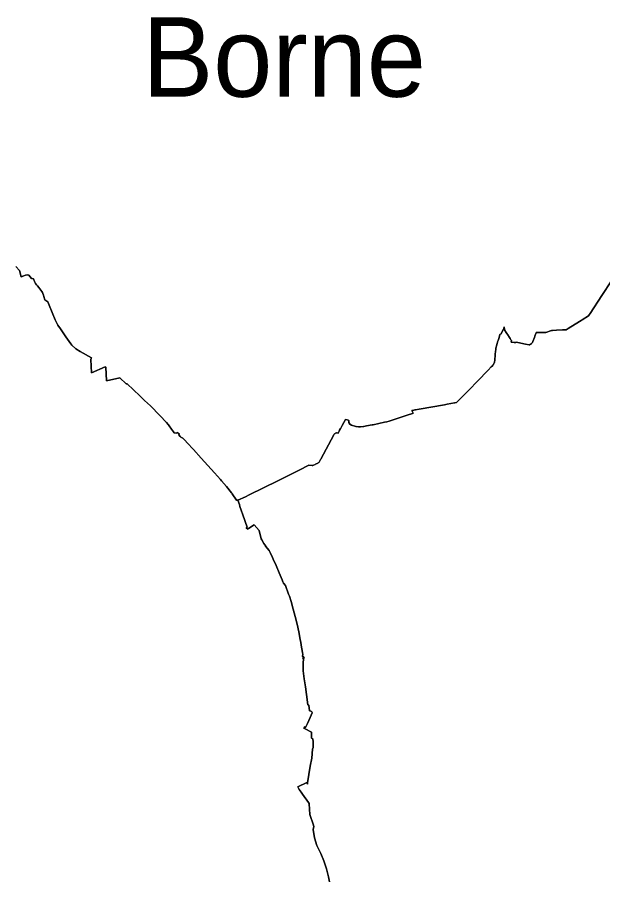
# Model space of a CAD drawing. Extents: x 113371 to 291721, y 393993 to 520143.
# Drawn here: x 246091 to 249775, y 475732 to 481156 of the extents above; entities that cross this region are included whole.
import ezdxf

# ---------------------------------------------------------------- set-up
doc = ezdxf.new("R2010")
doc.units = 0
doc.layers.add('Default', color=7, linetype='Continuous')
doc.layers.add('plaatsnamen', color=7, linetype='Continuous')

msp = doc.modelspace()

# ---------------------------------------------------------------- linework, layer by layer
at = {"layer": 'Default'}
for points in [[(246253.275625, 479417.4025), (246249.695625, 479425.5425), (246246.135625, 479431.3125), (246227.195625, 479457.0825), (246218.675625, 479466.1825), (246213.075625, 479472.6225), (246206.425625, 479481.6125), (246199.555625, 479494.6825), (246194.095625, 479509.9425), (246185.685625, 479512.2525), (246180.415625, 479513.7025), (246173.165625, 479523.2925), (246165.015625, 479532.7925), (246153.395625, 479536.4325), (246143.605625, 479534.5225), (246132.055625, 479529.7725), (246116.925625, 479522.3425), (246106.355625, 479563.2925), (246082.185625, 479588.5725)], [(246082.185625, 479588.5725), (246106.355625, 479563.2925), (246116.925625, 479522.3425), (246132.055625, 479529.7725), (246143.605625, 479534.5225), (246153.395625, 479536.4325), (246165.015625, 479532.7925), (246173.165625, 479523.2925), (246180.415625, 479513.7025), (246185.685625, 479512.2525), (246194.095625, 479509.9425), (246199.555625, 479494.6825), (246206.425625, 479481.6125), (246213.075625, 479472.6225), (246218.675625, 479466.1825), (246227.195625, 479457.0825), (246246.135625, 479431.3125), (246249.695625, 479425.5425), (246253.275625, 479417.4025), (246256.615625, 479408.5525), (246258.945625, 479399.9925), (246264.845625, 479378.1225), (246284.445625, 479365.7125), (246292.505625, 479344.5025), (246329.455625, 479252.2425)], [(249829.695625, 479499.0325), (249768.455625, 479405.4325), (249695.095625, 479293.2825), (249689.475625, 479284.7025), (249684.365625, 479276.8925), (249645.815625, 479253.0425), (249638.595625, 479248.7025), (249573.345625, 479208.2025), (249557.725625, 479198.5325), (249544.715625, 479190.4825), (249521.635625, 479190.8125), (249484.685625, 479187.6825), (249459.525625, 479186.1425), (249454.005625, 479185.8025), (249451.905625, 479185.1225)], [(249768.455625, 479405.4325), (249829.695625, 479499.0325)], [(247110.865625, 478535.6025), (247098.105625, 478544.6325), (247094.245625, 478540.2125), (247078.975625, 478542.3325), (247070.255625, 478554.1525), (247066.105625, 478559.9325), (247042.735625, 478592.4925), (247041.835625, 478593.6425), (247030.265625, 478606.4625), (246988.655625, 478651.2325), (246929.375625, 478711.8025), (246892.285625, 478745.5525), (246871.145625, 478766.7325), (246863.345625, 478774.5325), (246783.685625, 478850.5425), (246776.945625, 478850.7325), (246737.265625, 478888.7325), (246653.395625, 478868.2225), (246648.965625, 478955.5225), (246644.875625, 478957.4725), (246558.915625, 478919.6425), (246554.665625, 479004.0925), (246556.365625, 479009.9325), (246558.765625, 479014.3725), (246487.905625, 479054.6425), (246459.935625, 479070.5425), (246434.285625, 479093.6225), (246427.575625, 479101.8225), (246396.595625, 479146.2325), (246363.015625, 479196.7725), (246347.685625, 479219.7825), (246329.455625, 479252.2425), (246292.505625, 479344.5025), (246284.445625, 479365.7125), (246264.845625, 479378.1225), (246258.945625, 479399.9925), (246256.615625, 479408.5525), (246253.275625, 479417.4025)], [(249217.415625, 479110.1525), (249217.565625, 479110.1425), (249227.305625, 479109.1825), (249232.145625, 479111.4325), (249279.215625, 479101.7025), (249288.025625, 479099.8825), (249313.075625, 479096.3625), (249313.175625, 479096.3925), (249320.265625, 479098.8825), (249323.585625, 479100.6825), (249325.475625, 479102.0425), (249329.755625, 479105.1125), (249332.725625, 479110.6225), (249335.645625, 479116.5525), (249344.575625, 479140.8025), (249348.395625, 479151.0725), (249354.235625, 479166.8025), (249356.555625, 479172.0325), (249357.135625, 479172.9425), (249374.595625, 479173.2625), (249377.825625, 479173.3225), (249385.935625, 479173.4725), (249400.625625, 479173.7425), (249417.815625, 479174.0625), (249451.905625, 479185.1225), (249454.005625, 479185.8025), (249459.525625, 479186.1425), (249484.685625, 479187.6825), (249521.635625, 479190.8125), (249544.715625, 479190.4825), (249557.725625, 479198.5325), (249573.345625, 479208.2025), (249638.595625, 479248.7025), (249645.815625, 479253.0425), (249684.365625, 479276.8925), (249689.475625, 479284.7025), (249695.095625, 479293.2825), (249768.455625, 479405.4325)], [(246329.455625, 479252.2425), (246347.685625, 479219.7825), (246363.015625, 479196.7725), (246396.595625, 479146.2325), (246427.575625, 479101.8225), (246434.285625, 479093.6225), (246459.935625, 479070.5425), (246487.905625, 479054.6425), (246558.765625, 479014.3725), (246556.365625, 479009.9325), (246554.665625, 479004.0925), (246558.915625, 478919.6425), (246644.875625, 478957.4725), (246648.965625, 478955.5225), (246653.395625, 478868.2225), (246737.265625, 478888.7325), (246776.945625, 478850.7325), (246783.685625, 478850.5425), (246863.345625, 478774.5325), (246871.145625, 478766.7325), (246892.285625, 478745.5525), (246929.375625, 478711.8025), (246988.655625, 478651.2325), (247030.265625, 478606.4625), (247041.835625, 478593.6425), (247042.735625, 478592.4925), (247066.105625, 478559.9325), (247070.255625, 478554.1525), (247078.975625, 478542.3325), (247094.245625, 478540.2125), (247098.105625, 478544.6325), (247110.865625, 478535.6025), (247107.895625, 478530.3925), (247116.085625, 478518.1925), (247121.445625, 478514.5325), (247132.205625, 478507.8925), (247141.435625, 478499.3025), (247166.515625, 478472.9825)], [(249152.175625, 479200.3625), (249151.625625, 479199.0725), (249149.585625, 479194.3225), (249141.515625, 479180.1025), (249135.525625, 479165.4025), (249127.595625, 479160.1525), (249121.455625, 479134.1125), (249120.275625, 479136.0025), (249116.625625, 479123.5325), (249113.815625, 479114.0325), (249112.565625, 479109.5225), (249111.715625, 479106.4625), (249108.865625, 479096.2625), (249106.725625, 479088.9625), (249104.225625, 479080.5225), (249103.085625, 479075.3825), (249102.375625, 479071.2625), (249101.735625, 479066.8325), (249100.535625, 479052.6625), (249099.185625, 479037.2025), (249098.045625, 479022.0725), (249096.935625, 479009.3325), (249095.795625, 478996.4625), (249094.515625, 478989.3325), (249093.815625, 478987.0825), (249093.235625, 478984.9125), (249092.355625, 478982.7425), (249090.285625, 478977.9725), (249087.375625, 478972.4225), (249083.785625, 478967.3625), (249079.035625, 478961.5125), (249073.775625, 478956.2625), (249054.295625, 478936.1925), (249030.835625, 478912.2225), (249009.945625, 478890.6225), (248987.775625, 478868.0125), (248977.085625, 478857.0425), (248970.155625, 478849.9325)], [(249093.815625, 478987.0825), (249094.515625, 478989.3325), (249095.795625, 478996.4625), (249096.935625, 479009.3325), (249098.045625, 479022.0725), (249099.185625, 479037.2025), (249100.535625, 479052.6625), (249101.735625, 479066.8325), (249102.375625, 479071.2625), (249103.085625, 479075.3825), (249104.225625, 479080.5225), (249106.725625, 479088.9625), (249108.865625, 479096.2625), (249111.715625, 479106.4625), (249112.565625, 479109.5225), (249113.815625, 479114.0325), (249116.625625, 479123.5325), (249120.275625, 479136.0025), (249121.455625, 479134.1125), (249127.595625, 479160.1525), (249135.525625, 479165.4025), (249141.515625, 479180.1025), (249149.585625, 479194.3225), (249151.625625, 479199.0725), (249152.175625, 479200.3625), (249155.695625, 479208.9025), (249156.515625, 479191.6525), (249156.585625, 479190.3525), (249167.985625, 479172.5525), (249181.225625, 479151.5225), (249183.165625, 479148.4325), (249192.145625, 479134.3625), (249194.565625, 479130.3925), (249196.315625, 479127.5125), (249198.615625, 479125.2225), (249200.745625, 479123.2525), (249199.625625, 479112.0725), (249217.415625, 479110.1525)], [(249451.905625, 479185.1225), (249417.815625, 479174.0625), (249400.625625, 479173.7425), (249385.935625, 479173.4725), (249377.825625, 479173.3225), (249374.595625, 479173.2625), (249357.135625, 479172.9425), (249356.555625, 479172.0325), (249354.235625, 479166.8025), (249348.395625, 479151.0725), (249344.575625, 479140.8025), (249335.645625, 479116.5525), (249332.725625, 479110.6225), (249329.755625, 479105.1125), (249325.475625, 479102.0425), (249323.585625, 479100.6825), (249320.265625, 479098.8825), (249313.175625, 479096.3925), (249313.075625, 479096.3625), (249288.025625, 479099.8825), (249279.215625, 479101.7025), (249232.145625, 479111.4325), (249227.305625, 479109.1825), (249217.565625, 479110.1425), (249217.415625, 479110.1525), (249199.625625, 479112.0725), (249200.745625, 479123.2525), (249198.615625, 479125.2225), (249196.315625, 479127.5125), (249194.565625, 479130.3925), (249192.145625, 479134.3625), (249183.165625, 479148.4325), (249181.225625, 479151.5225), (249167.985625, 479172.5525), (249156.585625, 479190.3525), (249156.515625, 479191.6525), (249155.695625, 479208.9025), (249152.175625, 479200.3625)], [(248430.255625, 478614.9125), (248463.525625, 478625.8425), (248506.205625, 478639.8625), (248544.145625, 478652.3325), (248578.495625, 478663.6225), (248582.145625, 478664.8225), (248573.205625, 478682.4625), (248586.405625, 478684.8125), (248587.105625, 478684.9425), (248592.205625, 478685.8425), (248594.735625, 478686.2925), (248594.745625, 478686.3025), (248596.465625, 478686.6025), (248619.145625, 478690.6525), (248778.685625, 478719.0825), (248796.445625, 478722.2525), (248841.485625, 478730.2725), (248844.215625, 478730.7625), (248855.675625, 478732.8025), (248863.155625, 478740.3025), (248884.495625, 478762.1225), (248908.685625, 478786.8625), (248927.785625, 478806.5825), (248950.845625, 478830.1425), (248970.155625, 478849.9325), (248977.085625, 478857.0425), (248987.775625, 478868.0125), (249009.945625, 478890.6225), (249030.835625, 478912.2225), (249054.295625, 478936.1925), (249073.775625, 478956.2625), (249079.035625, 478961.5125), (249083.785625, 478967.3625), (249087.375625, 478972.4225), (249090.285625, 478977.9725), (249092.355625, 478982.7425), (249093.235625, 478984.9125), (249093.815625, 478987.0825)], [(248970.155625, 478849.9325), (248950.845625, 478830.1425), (248927.785625, 478806.5825), (248908.685625, 478786.8625), (248884.495625, 478762.1225), (248863.155625, 478740.3025), (248855.675625, 478732.8025), (248844.215625, 478730.7625), (248841.485625, 478730.2725), (248796.445625, 478722.2525), (248778.685625, 478719.0825), (248619.145625, 478690.6525), (248596.465625, 478686.6025), (248594.745625, 478686.3025), (248594.735625, 478686.2925), (248592.205625, 478685.8425), (248587.105625, 478684.9425), (248586.405625, 478684.8125), (248573.205625, 478682.4625), (248582.145625, 478664.8225), (248578.495625, 478663.6225), (248544.145625, 478652.3325), (248506.205625, 478639.8625), (248463.525625, 478625.8425), (248430.255625, 478614.9125), (248415.635625, 478611.7625), (248402.855625, 478609.0025), (248330.435625, 478593.3925), (248328.045625, 478592.9325), (248324.045625, 478592.1525), (248288.605625, 478585.3025), (248271.005625, 478581.6025), (248270.555625, 478581.5025), (248251.665625, 478579.0525), (248237.475625, 478579.1625), (248222.785625, 478581.2625), (248220.665625, 478581.5625), (248194.385625, 478590.2225)], [(248194.385625, 478590.2225), (248184.705625, 478595.7225), (248177.735625, 478606.2325), (248177.705625, 478612.2625), (248177.675625, 478620.0025), (248174.005625, 478621.0325), (248166.935625, 478623.0125), (248157.535625, 478625.6425), (248136.145625, 478587.4125), (248131.955625, 478580.0625), (248126.885625, 478571.1625), (248125.555625, 478568.8125), (248119.685625, 478558.3525), (248116.535625, 478553.0125), (248112.275625, 478543.9025), (248110.495625, 478540.0225), (248103.455625, 478541.3725), (248099.585625, 478541.7725), (248094.425625, 478540.8325), (248090.665625, 478538.9025), (248088.235625, 478536.8525), (248085.605625, 478533.2825), (248083.115625, 478528.7125), (248000.845625, 478377.3425), (247998.845625, 478373.6725), (247990.385625, 478358.1025), (247988.065625, 478354.8325), (247985.405625, 478352.4625), (247982.415625, 478350.7625), (247968.705625, 478344.7325), (247965.415625, 478343.2925), (247954.995625, 478338.7125), (247950.235625, 478337.4125), (247946.475625, 478337.3825), (247926.565625, 478337.9025), (247865.965625, 478307.9125), (247731.085625, 478241.1525), (247550.825625, 478152.3925)], [(247998.845625, 478373.6725), (248000.845625, 478377.3425), (248083.115625, 478528.7125), (248085.605625, 478533.2825), (248088.235625, 478536.8525), (248090.665625, 478538.9025), (248094.425625, 478540.8325), (248099.585625, 478541.7725), (248103.455625, 478541.3725), (248110.495625, 478540.0225), (248112.275625, 478543.9025), (248116.535625, 478553.0125), (248119.685625, 478558.3525), (248125.555625, 478568.8125), (248126.885625, 478571.1625), (248131.955625, 478580.0625), (248136.145625, 478587.4125), (248157.535625, 478625.6425), (248166.935625, 478623.0125), (248174.005625, 478621.0325), (248177.675625, 478620.0025), (248177.705625, 478612.2625), (248177.735625, 478606.2325), (248184.705625, 478595.7225), (248194.385625, 478590.2225), (248220.665625, 478581.5625), (248222.785625, 478581.2625), (248237.475625, 478579.1625), (248251.665625, 478579.0525), (248270.555625, 478581.5025), (248271.005625, 478581.6025), (248288.605625, 478585.3025), (248324.045625, 478592.1525), (248328.045625, 478592.9325), (248330.435625, 478593.3925), (248402.855625, 478609.0025), (248415.635625, 478611.7625), (248430.255625, 478614.9125)], [(247675.405625, 477801.5225), (247653.975625, 477828.7325), (247655.215625, 477829.5225), (247643.785625, 477846.4125), (247629.285625, 477869.6325), (247625.805625, 477876.0625), (247626.595625, 477876.5225), (247612.395625, 477927.5325), (247581.225625, 477963.1125), (247546.335625, 477940.9525), (247542.165625, 477935.4925), (247531.825625, 477944.6025), (247537.555625, 477947.9225), (247510.935625, 478026.3625), (247500.755625, 478055.1725), (247492.665625, 478079.2025), (247488.805625, 478091.4025), (247479.445625, 478117.9225), (247472.025625, 478118.3225), (247471.555625, 478118.3525), (247443.705625, 478157.9425), (247441.075625, 478161.6725), (247438.715625, 478165.0325), (247408.245625, 478204.5625), (247376.785625, 478240.7625), (247370.965625, 478249.2325), (247333.375625, 478291.1725), (247248.785625, 478383.5725), (247199.795625, 478436.9325), (247191.515625, 478445.9325), (247168.445625, 478470.8925), (247166.515625, 478472.9825), (247141.435625, 478499.3025), (247132.205625, 478507.8925), (247121.445625, 478514.5325), (247116.085625, 478518.1925), (247107.895625, 478530.3925), (247110.865625, 478535.6025)], [(247166.515625, 478472.9825), (247168.445625, 478470.8925), (247191.515625, 478445.9325), (247199.795625, 478436.9325), (247248.785625, 478383.5725), (247333.375625, 478291.1725), (247370.965625, 478249.2325), (247376.785625, 478240.7625), (247408.245625, 478204.5625), (247438.715625, 478165.0325), (247441.075625, 478161.6725), (247443.705625, 478157.9425), (247471.555625, 478118.3525), (247472.025625, 478118.3225), (247479.445625, 478117.9225), (247526.405625, 478140.3625), (247550.825625, 478152.3925), (247731.085625, 478241.1525), (247865.965625, 478307.9125), (247926.565625, 478337.9025), (247946.475625, 478337.3825), (247950.235625, 478337.4125), (247954.995625, 478338.7125), (247965.415625, 478343.2925), (247968.705625, 478344.7325), (247982.415625, 478350.7625), (247985.405625, 478352.4625), (247988.065625, 478354.8325), (247990.385625, 478358.1025), (247998.845625, 478373.6725)], [(247550.825625, 478152.3925), (247526.405625, 478140.3625), (247479.445625, 478117.9225), (247488.805625, 478091.4025), (247492.665625, 478079.2025), (247500.755625, 478055.1725), (247510.935625, 478026.3625), (247537.555625, 477947.9225), (247531.825625, 477944.6025), (247542.165625, 477935.4925), (247546.335625, 477940.9525), (247581.225625, 477963.1125), (247612.395625, 477927.5325), (247626.595625, 477876.5225), (247625.805625, 477876.0625), (247629.285625, 477869.6325), (247643.785625, 477846.4125), (247655.215625, 477829.5225), (247653.975625, 477828.7325), (247675.405625, 477801.5225), (247677.705625, 477797.9825), (247680.265625, 477793.5025), (247682.155625, 477789.7825), (247696.455625, 477757.3325), (247700.845625, 477747.9525), (247719.915625, 477707.2825), (247739.495625, 477662.4425), (247757.955625, 477617.1325), (247762.635625, 477605.0225), (247766.175625, 477595.8825), (247779.785625, 477582.1325), (247798.725625, 477527.6525), (247803.185625, 477514.5525), (247814.555625, 477481.1425), (247827.875625, 477433.8425), (247840.685625, 477386.4225), (247852.305625, 477338.6925), (247862.835625, 477290.6725)], [(247903.865625, 476945.4225), (247897.085625, 476994.9425), (247890.275625, 477044.3925), (247890.285625, 477102.7225), (247892.325625, 477112.7825), (247892.925625, 477115.7725), (247887.315625, 477126.9525), (247893.075625, 477126.5125), (247895.545625, 477125.9925), (247894.405625, 477133.6925), (247892.035625, 477134.1625), (247886.305625, 477136.0125), (247887.545625, 477149.6325), (247886.385625, 477158.3625), (247886.385625, 477158.3725), (247883.915625, 477174.0325), (247880.755625, 477193.5925), (247875.625625, 477223.2425), (247872.325625, 477242.3025), (247862.835625, 477290.6725), (247852.305625, 477338.6925), (247840.685625, 477386.4225), (247827.875625, 477433.8425), (247814.555625, 477481.1425), (247803.185625, 477514.5525), (247798.725625, 477527.6525), (247779.785625, 477582.1325), (247766.175625, 477595.8825), (247762.635625, 477605.0225), (247757.955625, 477617.1325), (247739.495625, 477662.4425), (247719.915625, 477707.2825), (247700.845625, 477747.9525), (247696.455625, 477757.3325), (247682.155625, 477789.7825), (247680.265625, 477793.5025), (247677.705625, 477797.9825), (247675.405625, 477801.5225)], [(247862.835625, 477290.6725), (247872.325625, 477242.3025), (247875.625625, 477223.2425), (247880.755625, 477193.5925), (247883.915625, 477174.0325), (247886.385625, 477158.3725), (247886.385625, 477158.3625), (247887.545625, 477149.6325), (247886.305625, 477136.0125), (247892.035625, 477134.1625), (247894.405625, 477133.6925), (247895.545625, 477125.9925), (247893.075625, 477126.5125), (247887.315625, 477126.9525), (247892.925625, 477115.7725), (247892.325625, 477112.7825), (247890.285625, 477102.7225), (247890.275625, 477044.3925), (247897.085625, 476994.9425), (247903.865625, 476945.4225), (247910.615625, 476895.9025), (247919.365625, 476831.5325), (247925.575625, 476830.3525), (247930.945625, 476793.0425), (247939.235625, 476791.7425), (247942.965625, 476790.0925), (247945.415625, 476787.1425), (247946.665625, 476783.7225), (247946.965625, 476780.4125), (247934.675625, 476751.0525), (247917.305625, 476713.4825), (247905.635625, 476688.6125), (247897.945625, 476692.5725), (247893.895625, 476684.8625), (247902.925625, 476679.7525), (247941.665625, 476659.4925), (247942.595625, 476621.1525), (247950.375625, 476617.2525)], [(247932.545625, 476142.4825), (247928.565625, 476209.5825), (247927.805625, 476210.8525), (247924.375625, 476216.5625), (247887.005625, 476269.0825), (247877.735625, 476281.8825), (247865.625625, 476300.1725), (247856.465625, 476315.5225), (247855.795625, 476316.8325), (247913.205625, 476342.2425), (247917.665625, 476333.5425), (247917.835625, 476342.4425), (247921.765625, 476366.5025), (247926.235625, 476393.9125), (247934.605625, 476445.4025), (247944.925625, 476497.1525), (247948.925625, 476552.3225), (247954.165625, 476563.0025), (247952.405625, 476598.9625), (247950.375625, 476617.2525), (247942.595625, 476621.1525), (247941.665625, 476659.4925), (247902.925625, 476679.7525), (247893.895625, 476684.8625), (247897.945625, 476692.5725), (247905.635625, 476688.6125), (247917.305625, 476713.4825), (247934.675625, 476751.0525), (247946.965625, 476780.4125), (247946.665625, 476783.7225), (247945.415625, 476787.1425), (247942.965625, 476790.0925), (247939.235625, 476791.7425), (247930.945625, 476793.0425), (247925.575625, 476830.3525), (247919.365625, 476831.5325), (247910.615625, 476895.9025), (247903.865625, 476945.4225)], [(247950.375625, 476617.2525), (247952.405625, 476598.9625), (247954.165625, 476563.0025), (247948.925625, 476552.3225), (247944.925625, 476497.1525), (247934.605625, 476445.4025), (247926.235625, 476393.9125), (247921.765625, 476366.5025), (247917.835625, 476342.4425), (247917.665625, 476333.5425), (247913.205625, 476342.2425), (247855.795625, 476316.8325), (247856.465625, 476315.5225), (247865.625625, 476300.1725), (247877.735625, 476281.8825), (247887.005625, 476269.0825), (247924.375625, 476216.5625), (247927.805625, 476210.8525), (247928.565625, 476209.5825), (247932.545625, 476142.4825), (247932.635625, 476140.9925), (247955.085625, 476075.0925), (247957.095625, 476063.5725), (247953.595625, 476050.2825), (247953.015625, 476048.1125), (247962.395625, 475996.0525), (247976.985625, 475947.3625), (248000.685625, 475897.4525), (248019.895625, 475849.7525), (248036.085625, 475801.1525), (248048.895625, 475750.5525), (248055.505625, 475717.9025)], [(248055.505625, 475717.9025), (248048.895625, 475750.5525), (248036.085625, 475801.1525), (248019.895625, 475849.7525), (248000.685625, 475897.4525), (247976.985625, 475947.3625), (247962.395625, 475996.0525), (247953.015625, 476048.1125), (247953.595625, 476050.2825), (247957.095625, 476063.5725), (247955.085625, 476075.0925), (247932.635625, 476140.9925), (247932.545625, 476142.4825)]]:
    msp.add_lwpolyline(points, dxfattribs=at)

# ---------------------------------------------------------------- texts
at = {"layer": 'plaatsnamen'}
msp.add_text('Borne', height=500, dxfattribs=at).set_placement((246878.468781, 480655.646476))

doc.saveas('drawing.dxf')
